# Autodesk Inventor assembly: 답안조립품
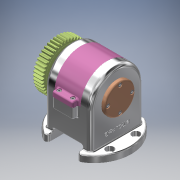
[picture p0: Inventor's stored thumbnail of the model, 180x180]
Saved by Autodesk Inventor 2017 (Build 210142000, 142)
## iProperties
Part Number: 답안조립품
Material: 일반
Document SubType Name: Assembly
Designer: MRC
Author: MRC
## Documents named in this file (21)
- C:\Users\MRC\Desktop\740804V1007\답안조립품.iam
- C:\Users\MRC\Desktop\740804V1007\본체.ipt
- C:\Users\MRC\Desktop\740804V1007\오일레스 부시 20 15.ipt
- C:\Users\MRC\Desktop\740804V1007\부시 커버.ipt
- C:\Users\MRC\Desktop\740804V1007\육각 소켓 머리 볼트 M4x10.ipt
- C:\Users\MRC\Desktop\740804V1007\링크.ipt
- C:\Users\MRC\Desktop\740804V1007\펀치.ipt
- C:\Users\MRC\Desktop\740804V1007\핀.ipt
- C:\Users\MRC\Desktop\740804V1007\E형 멈춤링 10-8.ipt
- C:\Users\MRC\Desktop\740804V1007\깊은 홈 볼 베어링 6904.ipt
- C:\Users\MRC\Desktop\740804V1007\칼라.ipt
- C:\Users\MRC\Desktop\740804V1007\편심축.ipt
- C:\Users\MRC\Desktop\740804V1007\뒷커버.ipt
- C:\Users\MRC\Desktop\740804V1007\오일실 20 32 5.ipt
- C:\Users\MRC\Desktop\740804V1007\앞커버.ipt
- C:\Users\MRC\Desktop\740804V1007\평행키 5x5x12.ipt
- C:\Users\MRC\Desktop\740804V1007\스퍼 기어.ipt
- C:\Users\MRC\Desktop\740804V1007\스프링 와셔 M10.ipt
- C:\Users\MRC\Desktop\740804V1007\윗커버.ipt
- C:\Users\MRC\Desktop\740804V1007\육각 너트 M10x1.ipt
- C:\Users\MRC\Desktop\740804V1007\평와셔 M10.ipt
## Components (2 placed, 2 different names)
1. 핀:1
2. E형 멈춤링 10-8:1
